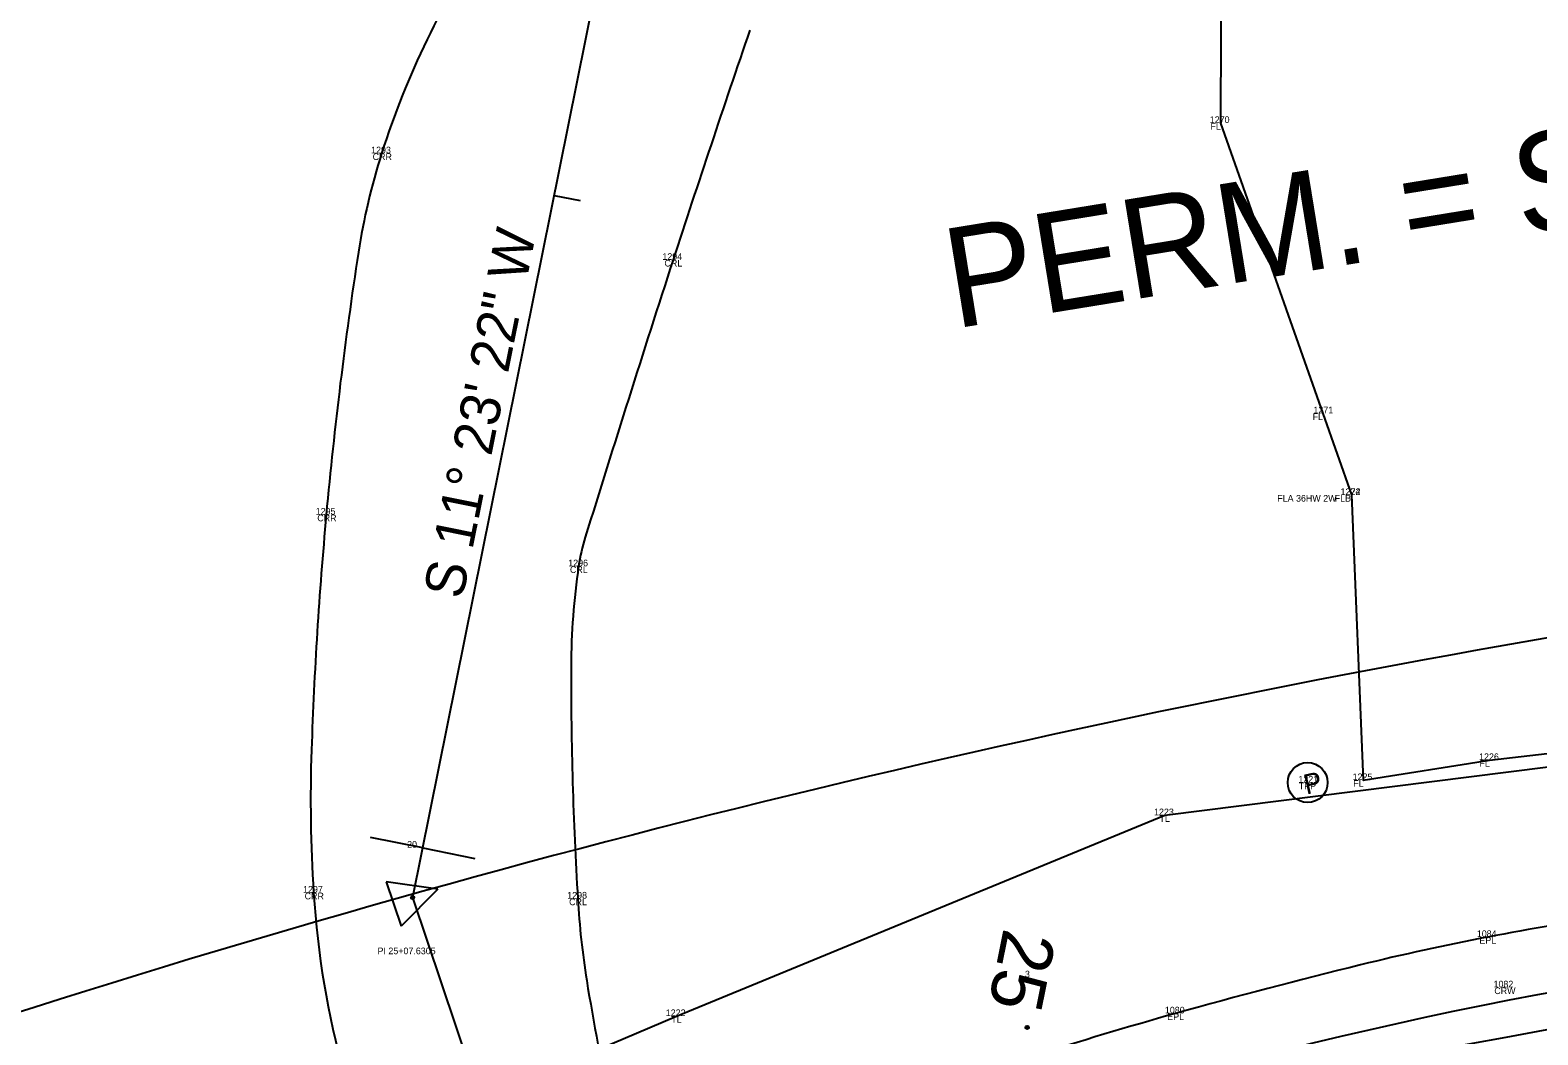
# Model space of a CAD drawing. Extents: x 1965498 to 1971309, y 1116335 to 1119906.
# Drawn here: x 1967747.3 to 1967973.9, y 1117914.3 to 1118065.2 of the extents above; entities that cross this region are included whole.
import ezdxf

# ---------------------------------------------------------------- set-up
doc = ezdxf.new("R2010")
doc.units = 0
for name, color, linetype in [('Level 1', 7, 'Continuous'), ('Level 10', 7, 'Continuous'), ('Level 11', 7, 'Continuous'), ('Level 12', 7, 'Continuous'), ('Level 15', 7, 'Continuous'), ('Level 19', 7, 'Continuous'), ('Level 21', 7, 'Continuous'), ('Level 3', 7, 'Continuous'), ('Level 33', 7, 'Continuous'), ('Level 50', 7, 'Continuous'), ('Level 51', 7, 'Continuous'), ('Level 53', 7, 'Continuous'), ('Level 58', 7, 'Continuous'), ('Level 59', 7, 'Continuous'), ('Level 60', 7, 'Continuous'), ('Level 61', 7, 'Continuous'), ('Level 8', 7, 'Continuous'), ('Level 9', 7, 'Continuous')]:
    doc.layers.add(name, color=color, linetype=linetype)

msp = doc.modelspace()

# ---------------------------------------------------------------- linework, layer by layer
at = {"layer": 'Level 1'}
for p, q in [((1967834.04, 1118079.96), (1967804.81, 1117934.87)), ((1967826.06, 1118040.38), (1967829.99, 1118039.59)), ((1967806.32, 1117942.35), (1967798.47, 1117943.93)), ((1967806.32, 1117942.35), (1967814.16, 1117940.77)), ((1967800.85, 1117937.24), (1967803.08, 1117930.6)), ((1967808.6, 1117936.14), (1967800.85, 1117937.24)), ((1967808.6, 1117936.14), (1967803.08, 1117930.6)), ((1967804.81, 1117934.87), (1967849.81, 1117800.6))]:
    msp.add_line(p, q, dxfattribs=at)
msp.add_circle((1967804.81, 1117934.87), 0.25, dxfattribs=at)
msp.add_arc((1968094.39, 1117277.53), 653.93, 87.72663, 111.99584, dxfattribs=at)
at = {"layer": 'Level 10'}
for centre, radius, start, end in [((1967924.21, 1118007.05), 130.24, 146.084, 162.2789), ((1969955.94, 1117343.65), 2220.92, 161.04122, 161.97992), ((1967892.8, 1118017.09), 97.26, 162.2789, 171.2815), ((1968447.32, 1117932.05), 658.27, 171.28154, 174.73903), ((1970536.08, 1117154.93), 2830.98, 161.97992, 162.86471), ((1968396.68, 1117936.71), 607.41, 174.73903, 178.08012), ((1967859.17, 1117980.26), 29.73, 162.8647, 171.5072), ((1967932.18, 1117969.36), 103.55, 171.5072, 179.8469), ((1968385.41, 1117968.14), 556.78, 179.8469, 183.4407), ((1968012.41, 1117949.59), 222.93, 178.0801, 183.5965), ((1967922.97, 1117943.97), 133.3, 183.5965, 195.4685), ((1967954.76, 1117942.25), 125.36, 183.4407, 189.0928), ((1968136.99, 1117971.42), 309.91, 189.0928, 192.6866)]:
    msp.add_arc(centre, radius, start, end, dxfattribs=at)
at = {"layer": 'Level 11'}
msp.add_lwpolyline([(1967422.03, 1117809.72), (1967453.38, 1117748.92), (1967559.8, 1117796.17), (1967844.47, 1117917.07), (1967917.86, 1117947.25), (1968009.67, 1117958.84), (1968061.48, 1117958.08), (1968105.8, 1117963.33), (1968158.86, 1117956.79), (1968212.37, 1117954.08), (1968423.16, 1117946.63), (1968536.42, 1117942.26)], dxfattribs=at)
at = {"layer": 'Level 12'}
for p, q in [((1967834.04, 1118079.96), (1967804.81, 1117934.87)), ((1967804.81, 1117934.87), (1967825.19, 1117874.05))]:
    msp.add_line(p, q, dxfattribs=at)
for centre, radius in [((1967897.18, 1117915.38), 0.25), ((1967897.17, 1117915.38), 0.02), ((1967897.17, 1117915.38), 0.0001)]:
    msp.add_circle(centre, radius, dxfattribs=at)
at = {"layer": 'Level 15'}
msp.add_arc((1968266.61, 1116286.83), 1654.02, 97.99689, 110.59689, dxfattribs=at)
at = {"layer": 'Level 19'}
msp.add_arc((1968266.61, 1116286.83), 1637.02, 87.72663, 111.99584, dxfattribs=at)
at = {"layer": 'Level 3'}
for centre, radius, start, end in [((1968039.2, 1117551.01), 384.88, 97.9635, 100.9026), ((1968040.96, 1117541.9), 394.16, 100.9026, 103.7451), ((1968149.84, 1117096.77), 852.41, 103.74512, 105.67793), ((1968090.83, 1117307.02), 634.04, 105.67793, 107.70681)]:
    msp.add_arc(centre, radius, start, end, dxfattribs=at)
at = {"layer": 'Level 33'}
msp.add_arc((1968266.61, 1116286.83), 1712.02, 94.56706, 111.99584, dxfattribs=at)
at = {"layer": 'Level 50'}
for centre in [(1967926.25, 1118051.25), (1967800.15, 1118046.69), (1967843.96, 1118030.69), (1967941.61, 1118007.63), (1967945.93, 1117995.37), (1967945.93, 1117995.37), (1967791.83, 1117992.41), (1967829.77, 1117984.65), (1967966.69, 1117955.54), (1967947.71, 1117952.52), (1967917.86, 1117947.25), (1967789.93, 1117935.61), (1967804.81, 1117934.87), (1967829.63, 1117934.73), (1967966.4, 1117928.95), (1967968.89, 1117921.38), (1967844.47, 1117917.07), (1967919.49, 1117917.47), (1967897.17, 1117915.38)]:
    msp.add_circle(centre, 0.001, dxfattribs=at)
at = {"layer": 'Level 8'}
for points in [[(1967920.92, 1118368.66), (1967937.87, 1118342.4), (1967954.81, 1118301.31), (1967965.67, 1118250.56), (1967963.61, 1118188.09), (1967935.71, 1118144.56), (1967926.43, 1118106.38), (1967926.25, 1118051.25), (1967941.61, 1118007.63), (1967945.93, 1117995.37)], [(1967945.93, 1117995.37), (1967947.71, 1117952.52), (1967966.69, 1117955.54), (1968009.98, 1117960.51), (1968062.77, 1117959.8), (1968105.6, 1117961.86), (1968158.55, 1117958.33), (1968214.15, 1117955.95), (1968422.33, 1117947.89), (1968537.53, 1117942.88)]]:
    msp.add_lwpolyline(points, dxfattribs=at)
at = {"layer": 'Level 9'}
msp.add_circle((1967939.34, 1117952.16), 3, dxfattribs=at)

# ---------------------------------------------------------------- texts
at = {"layer": 'Level 21'}
for s, height, rotation, p in [('S 11%%d 23\' 22" W', 6, 78.6104, (1967812.28, 1117979.56)), ('25', 8, 258.6104, (1967893.69, 1117930.46))]:
    msp.add_text(s, height=height, rotation=rotation, dxfattribs=at).set_placement(p)
at = {"layer": 'Level 33'}
msp.add_text('PERM. = SLOPE, EROSION CONTROL, DRAINAGE, ENTRANCE', height=15, rotation=9.2399, dxfattribs=at).set_placement((1967886.22, 1118020.34))
at = {"layer": 'Level 51'}
for s, p in [('20', (1967803.98, 1117942.37)), ('PI 25+07.6305', (1967799.53, 1117926.37)), ('3', (1967896.84, 1117922.88))]:
    msp.add_text(s, height=1, dxfattribs=at).set_placement(p)
at = {"layer": 'Level 53'}
for s, p in [('1084', (1967964.77, 1117928.95)), ('EPL', (1967965.15, 1117927.95)), ('1082', (1967967.28, 1117921.38)), ('CRW', (1967967.4, 1117920.38)), ('1080', (1967917.88, 1117917.47)), ('EPL', (1967918.24, 1117916.47))]:
    msp.add_text(s, height=1, dxfattribs=at).set_placement(p)
at = {"layer": 'Level 58'}
for s, p in [('1270', (1967924.63, 1118051.25)), ('FL', (1967924.73, 1118050.25)), ('FL', (1967940.09, 1118006.63)), ('1271', (1967940.21, 1118007.63)), ('1224', (1967944.29, 1117995.37)), ('1272', (1967944.31, 1117995.37)), ('FLA 36HW 2W', (1967934.77, 1117994.37)), ('FLB', (1967943.41, 1117994.37)), ('1226', (1967965.11, 1117955.54)), ('FL', (1967965.17, 1117954.54)), ('1225', (1967946.1, 1117952.52)), ('FL', (1967946.19, 1117951.52))]:
    msp.add_text(s, height=1, dxfattribs=at).set_placement(p)
at = {"layer": 'Level 59'}
for s, p in [('1221', (1967937.95, 1117952.16)), ('TPP', (1967938.01, 1117951.16))]:
    msp.add_text(s, height=1, dxfattribs=at).set_placement(p)
at = {"layer": 'Level 60'}
for s, p in [('CRR', (1967798.8, 1118045.69)), ('CRL', (1967842.66, 1118029.69)), ('CRR', (1967790.48, 1117991.41)), ('CRL', (1967828.46, 1117983.65)), ('CRR', (1967788.58, 1117934.61)), ('CRL', (1967828.33, 1117933.73))]:
    msp.add_text(s, height=1, dxfattribs=at).set_placement(p)
at = {"layer": 'Level 61'}
for s, p in [('1293', (1967798.57, 1118046.69)), ('1294', (1967842.35, 1118030.69)), ('1295', (1967790.24, 1117992.41)), ('1296', (1967828.2, 1117984.65)), ('1223', (1967916.25, 1117947.25)), ('TL', (1967917.07, 1117946.25)), ('1297', (1967788.34, 1117935.61)), ('1298', (1967828.05, 1117934.73)), ('1222', (1967842.86, 1117917.07)), ('TL', (1967843.69, 1117916.07))]:
    msp.add_text(s, height=1, dxfattribs=at).set_placement(p)
at = {"layer": 'Level 9'}
msp.add_text('P', height=3, rotation=12.9494, dxfattribs=at).set_placement((1967939.15, 1117950.34))

doc.saveas('drawing.dxf')
